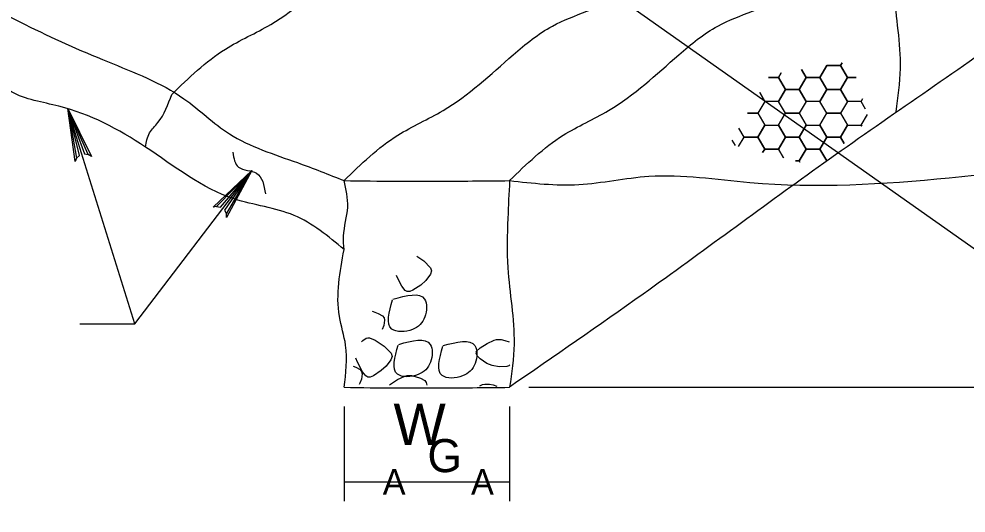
# Model space of a CAD drawing. Extents: x 3 to 3592, y -602 to 1171.
# Drawn here: x 3097.9 to 3183.7, y -382.5 to -337.7 of the extents above; entities that cross this region are included whole.
import ezdxf

# ---------------------------------------------------------------- set-up
doc = ezdxf.new("R2010")
doc.units = 0
for name, color, linetype in [('1', 7, 'Continuous'), ('2', 7, 'Continuous'), ('3', 7, 'Continuous')]:
    doc.layers.add(name, color=color, linetype=linetype)

msp = doc.modelspace()

# ---------------------------------------------------------------- linework, layer by layer
at = {"layer": '1'}
msp.add_line((2687.879, -7.809), (3528.879, -601.809), dxfattribs=at)
at = {"layer": '2'}
for p, q in [((3144.079, -371.112), (3209.548, -371.112)), ((3127.329, -372.862), (3127.329, -381.445)), ((3142.329, -372.862), (3142.329, -381.445)), ((3127.329, -379.695), (3142.329, -379.695))]:
    msp.add_line(p, q, dxfattribs=at)
for points in [[(3172.479, -341.662), (3172.329, -341.921)], [(3172.329, -341.921), (3172.479, -341.662)], [(3169.204, -343.004), (3168.785, -342.278)], [(3168.785, -342.278), (3169.204, -343.004)], [(3171.079, -341.921), (3170.454, -343.004)], [(3170.454, -343.004), (3171.079, -341.921)], [(3171.079, -341.921), (3171.065, -341.897)], [(3171.065, -341.897), (3171.079, -341.921)], [(3172.329, -341.921), (3171.079, -341.921)], [(3171.079, -341.921), (3172.329, -341.921)], [(3172.954, -343.004), (3172.329, -341.921)], [(3172.329, -341.921), (3172.954, -343.004)], [(3166.704, -343.004), (3165.802, -343.004)], [(3165.802, -343.004), (3166.704, -343.004)], [(3166.947, -342.584), (3166.704, -343.004)], [(3166.704, -343.004), (3166.947, -342.584)], [(3167.329, -344.086), (3166.704, -343.004)], [(3166.704, -343.004), (3167.329, -344.086)], [(3169.204, -343.004), (3168.579, -344.086)], [(3170.454, -343.004), (3169.204, -343.004)], [(3171.079, -344.086), (3170.454, -343.004)], [(3172.954, -343.004), (3172.329, -344.086)], [(3172.329, -344.086), (3172.954, -343.004)], [(3173.748, -343.004), (3172.954, -343.004)], [(3172.954, -343.004), (3173.748, -343.004)], [(3167.329, -344.086), (3166.704, -345.169)], [(3168.579, -344.086), (3167.329, -344.086)], [(3172.329, -344.086), (3171.079, -344.086)], [(3172.954, -345.169), (3172.329, -344.086)], [(3165.454, -345.169), (3164.999, -344.38)], [(3164.999, -344.38), (3165.454, -345.169)], [(3174.331, -344.949), (3174.204, -345.169)], [(3174.204, -345.169), (3174.331, -344.949)], [(3103.087, -350.338), (3103.35, -350.078), (3102.279, -345.833), (3103.087, -350.338), (3102.966, -350.619), (3102.279, -345.833), (3103.786, -349.939), (3104.144, -349.994), (3102.279, -345.833), (3104.424, -350.164), (3104.144, -349.994)], [(3165.454, -345.169), (3164.829, -346.251)], [(3166.704, -345.169), (3165.454, -345.169)], [(3174.204, -345.169), (3172.954, -345.169)], [(3174.606, -345.865), (3174.204, -345.169)], [(3103.373, -365.355), (3108.373, -365.355), (3102.331, -345.986)], [(3163.907, -346.251), (3164.829, -346.251)], [(3164.829, -346.251), (3163.907, -346.251)], [(3164.829, -346.251), (3165.454, -347.334)], [(3174.204, -347.334), (3174.758, -346.373)], [(3163.579, -348.416), (3163.114, -347.611)], [(3165.454, -347.334), (3164.829, -348.416)], [(3172.329, -348.416), (3172.954, -347.334)], [(3172.954, -347.334), (3174.204, -347.334)], [(3174.204, -347.334), (3174.247, -347.409)], [(3174.247, -347.409), (3174.204, -347.334)], [(3163.091, -349.262), (3163.579, -348.416)], [(3164.829, -348.416), (3163.579, -348.416)], [(3163.579, -348.416), (3164.829, -348.416)], [(3164.829, -348.416), (3165.454, -349.499)], [(3166.704, -349.499), (3167.329, -348.416)], [(3167.329, -348.416), (3168.579, -348.416)], [(3168.579, -348.416), (3169.204, -349.499)], [(3170.454, -349.499), (3171.079, -348.416)], [(3171.079, -348.416), (3172.329, -348.416)], [(3172.329, -348.416), (3172.663, -348.994)], [(3172.663, -348.994), (3172.329, -348.416)], [(3162.486, -348.688), (3162.77, -349.18)], [(3165.454, -349.499), (3165.27, -349.818)], [(3165.27, -349.818), (3165.454, -349.499)], [(3165.454, -349.499), (3166.704, -349.499)], [(3167.169, -350.303), (3166.704, -349.499)], [(3166.704, -349.499), (3167.169, -350.303)], [(3169.204, -349.499), (3168.579, -350.581)], [(3168.579, -350.581), (3169.204, -349.499)], [(3169.204, -349.499), (3170.454, -349.499)], [(3170.454, -349.499), (3171.078, -350.579)], [(3171.078, -350.579), (3170.454, -349.499)], [(3168.579, -350.581), (3168.258, -350.581)], [(3168.258, -350.581), (3168.579, -350.581)], [(3168.634, -350.677), (3168.579, -350.581)], [(3168.579, -350.581), (3168.634, -350.677)], [(3108.373, -365.355), (3118.97, -351.443)], [(3115.765, -354.71), (3116.129, -354.774), (3118.97, -351.443), (3115.765, -354.71), (3115.466, -354.774), (3118.97, -351.443), (3116.495, -355.048), (3116.657, -355.372), (3118.97, -351.443), (3116.681, -355.7), (3116.657, -355.372)], [(3133.915, -359.199), (3134.544, -359.63)], [(3134.544, -359.63), (3135.175, -360.258)], [(3135.249, -360.543), (3135.153, -360.846)], [(3135.175, -360.258), (3135.249, -360.543)], [(3132.105, -361.06), (3132.073, -360.973)], [(3132.558, -361.929), (3132.105, -361.06)], [(3134.725, -361.425), (3134.276, -361.838)], [(3135.153, -360.846), (3134.725, -361.425)], [(3132.878, -362.314), (3132.558, -361.929)], [(3134.276, -361.838), (3133.572, -362.3)], [(3133.054, -362.419), (3132.878, -362.314)], [(3133.275, -362.413), (3133.054, -362.419)], [(3133.572, -362.3), (3133.275, -362.413)], [(3129.859, -364.211), (3129.953, -364.231)], [(3129.953, -364.231), (3130.422, -364.402)], [(3130.422, -364.402), (3130.816, -364.616)], [(3130.816, -364.616), (3130.957, -364.793)], [(3130.957, -364.793), (3131, -365.017)], [(3130.93, -365.497), (3130.787, -365.876)], [(3131, -365.017), (3130.93, -365.497)], [(3128.917, -366.978), (3129.025, -366.871)], [(3129.025, -366.871), (3129.336, -366.664)], [(3129.336, -366.664), (3129.491, -366.62)], [(3129.491, -366.62), (3129.643, -366.627)], [(3129.643, -366.627), (3130.154, -366.832)], [(3130.154, -366.832), (3130.971, -367.392)], [(3130.971, -367.392), (3131.602, -368.021)], [(3139.657, -367.541), (3140.287, -367.124)], [(3140.287, -367.124), (3140.937, -366.83)], [(3140.937, -366.83), (3141.151, -366.777)], [(3141.151, -366.777), (3141.566, -366.781)], [(3141.566, -366.781), (3141.892, -366.849)], [(3141.892, -366.849), (3142.279, -366.99)], [(3131.602, -368.021), (3131.676, -368.306)], [(3139.281, -367.901), (3139.657, -367.541)], [(3139.427, -368.275), (3139.281, -367.981)], [(3139.652, -368.533), (3139.427, -368.275)], [(3128.532, -368.822), (3128.406, -368.481)], [(3128.986, -369.691), (3128.532, -368.822)], [(3131.58, -368.608), (3131.152, -369.187)], [(3131.676, -368.306), (3131.58, -368.608)], [(3140.268, -368.937), (3139.652, -368.533)], [(3140.747, -369.12), (3140.268, -368.937)], [(3141.387, -369.255), (3140.747, -369.12)], [(3142.254, -369.147), (3142.089, -369.234)], [(3142.339, -369.063), (3142.254, -369.147)], [(3128.164, -369.19), (3128.385, -369.271)], [(3128.385, -369.271), (3128.779, -369.485)], [(3128.779, -369.485), (3128.919, -369.662)], [(3128.962, -369.886), (3128.893, -370.366)], [(3128.919, -369.662), (3128.962, -369.886)], [(3129.305, -370.076), (3128.986, -369.691)], [(3130.703, -369.6), (3130, -370.062)], [(3131.152, -369.187), (3130.703, -369.6)], [(3142.089, -369.234), (3141.387, -369.255)], [(3128.749, -370.745), (3128.681, -370.855)], [(3128.893, -370.366), (3128.749, -370.745)], [(3129.482, -370.182), (3129.305, -370.076)], [(3129.702, -370.176), (3129.482, -370.182)], [(3130, -370.062), (3129.702, -370.176)], [(3131.46, -370.888), (3131.542, -370.81)], [(3131.542, -370.81), (3132.171, -370.393)], [(3132.171, -370.393), (3132.822, -370.1)], [(3132.822, -370.1), (3133.035, -370.046)], [(3133.035, -370.046), (3133.451, -370.051)], [(3133.451, -370.051), (3133.776, -370.118)], [(3133.776, -370.118), (3134.246, -370.289)], [(3134.246, -370.289), (3134.64, -370.504)], [(3134.64, -370.504), (3134.78, -370.681)], [(3134.78, -370.681), (3134.823, -370.904)], [(3139.625, -370.986), (3139.887, -370.867)], [(3139.887, -370.867), (3140.1, -370.814)], [(3140.1, -370.814), (3140.516, -370.818)], [(3140.516, -370.818), (3140.841, -370.886)], [(3134.823, -370.904), (3134.82, -370.928)], [(3140.841, -370.886), (3141.165, -371.004)]]:
    msp.add_lwpolyline(points, dxfattribs=at)
for points in [[(3168.579, -344.086), (3169.204, -343.004), (3170.454, -343.004), (3171.079, -344.086), (3170.454, -345.169), (3169.204, -345.169)], [(3166.704, -345.169), (3167.329, -344.086), (3168.579, -344.086), (3169.204, -345.169), (3168.579, -346.251), (3167.329, -346.251)], [(3170.454, -345.169), (3171.079, -344.086), (3172.329, -344.086), (3172.954, -345.169), (3172.329, -346.251), (3171.079, -346.251)], [(3166.704, -347.334), (3167.329, -346.251), (3168.579, -346.251), (3169.204, -347.334), (3168.579, -348.416), (3167.329, -348.416)], [(3170.454, -347.334), (3171.079, -346.251), (3172.329, -346.251), (3172.954, -347.334), (3172.329, -348.416), (3171.079, -348.416)], [(3164.829, -348.416), (3165.454, -347.334), (3166.704, -347.334), (3167.329, -348.416), (3166.704, -349.499), (3165.454, -349.499)], [(3168.579, -348.416), (3169.204, -347.334), (3170.454, -347.334), (3171.079, -348.416), (3170.454, -349.499), (3169.204, -349.499)]]:
    msp.add_lwpolyline(points, close=True, dxfattribs=at)
for points in [[(3111.704, -344.549), (3116.565, -340.436), (3120.679, -338.192), (3127.036, -333.143), (3130.589, -330.526), (3136.759, -327.721), (3139.751, -324.916), (3142.556, -321.924), (3147.418, -318.746), (3153.588, -315.006), (3160.132, -309.77), (3166.677, -305.47), (3172.847, -301.169), (3181.704, -294.549)], [(3127.329, -352.362), (3132.19, -348.248), (3136.304, -346.004), (3142.661, -340.956), (3146.214, -338.338), (3152.384, -335.533), (3155.376, -332.729), (3158.181, -329.737), (3163.043, -326.558), (3169.213, -322.819), (3175.757, -317.583), (3182.302, -313.282), (3188.472, -308.982), (3197.329, -302.362)], [(3142.329, -352.362), (3147.19, -348.248), (3151.304, -346.004), (3157.661, -340.956), (3161.214, -338.338), (3167.384, -335.533), (3170.376, -332.729), (3173.181, -329.737), (3178.043, -326.558), (3184.213, -322.819), (3190.757, -317.583), (3197.302, -313.282), (3203.472, -308.982), (3212.329, -302.362)], [(3064.829, -321.112), (3073.362, -325.114), (3081.402, -329.415), (3086.263, -331.845), (3091.686, -334.65), (3098.417, -338.203), (3105.897, -341.569), (3112.815, -344.934), (3116.929, -348.113), (3123.099, -350.731), (3127.329, -352.362)], [(3212.334, -321.086), (3187.165, -339.362), (3170.293, -351.153), (3154.44, -362.652), (3142.333, -371.088)], [(3127.329, -358.612), (3122.793, -355.517), (3117.371, -354.021), (3109.323, -349.312), (3101.477, -345.607), (3097.177, -344.298), (3093.698, -341.499), (3086.706, -339.062), (3082.779, -336.257), (3078.073, -333.687), (3072.308, -331.957), (3068.194, -328.217), (3062.448, -325.874)], [(3177.329, -327.362), (3177.171, -330.779), (3177.171, -335.267), (3177.732, -342.185), (3177.329, -346.112)], [(3109.323, -349.312), (3109.705, -348.037), (3110.453, -347.102), (3111.704, -344.549)], [(3117.231, -349.793), (3117.77, -351.142), (3119.389, -351.681), (3120.198, -353.57)], [(3142.329, -352.362), (3148.597, -352.712), (3154.955, -351.964), (3164.117, -352.525), (3200.255, -350.425), (3223.963, -350.861)], [(3127.329, -358.612), (3127.281, -357.386), (3127.655, -354.769), (3127.329, -352.362)], [(3127.329, -352.362), (3132.074, -352.414), (3135.627, -352.414), (3142.329, -352.362)], [(3142.329, -352.362), (3142.171, -355.779), (3142.171, -360.267), (3142.732, -367.185), (3142.329, -371.112)], [(3127.329, -371.112), (3127.468, -367.297), (3126.907, -364.679), (3127.329, -358.612)], [(3131.762, -363.117), (3134.629, -363.117), (3134.65, -364.732), (3133.519, -365.863), (3131.661, -365.823), (3131.721, -363.177)], [(3132.277, -367.213), (3135.145, -367.213), (3135.165, -368.829), (3134.034, -369.96), (3132.176, -369.92), (3132.237, -367.274)], [(3136.319, -367.331), (3139.187, -367.331), (3139.207, -368.947), (3138.076, -370.078), (3136.218, -370.038), (3136.278, -367.392)], [(3127.329, -371.112), (3132.074, -371.164), (3135.627, -371.164), (3142.329, -371.112)]]:
    msp.add_spline(points, degree=3, dxfattribs=at)

# ---------------------------------------------------------------- texts
for p in [(3130.828, -380.861), (3138.829, -380.861)]:
    msp.add_text('A', height=2.333, dxfattribs=at).set_placement(p)
at = {"layer": '3'}
for s, height, p in [('W', 3.749, (3131.811, -376.355)), ('G', 2.999, (3134.889, -378.808))]:
    msp.add_text(s, height=height, dxfattribs=at).set_placement(p)

doc.saveas('drawing.dxf')
